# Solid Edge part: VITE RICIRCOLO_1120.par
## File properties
Subject: VITE RICIRCOLO 1120
Author: f_grande
Template: Normal.par
Last saved by: f_grande
Revision: 3
Application: Solid Edge
Material: Acciaio
Stile della faccia: Acciaio
Stile di riempimento: ANSI32(Acciaio)
Stile virtuale: Acciaio lavorato a macchina
Coef. of Thermal Exp: 0.0
Thermal Conductivity: 32.0
Specific Heat: 481.0
Modulus of Elasticity: 199947953000.0
Poisson's Ratio: 0.29
Yield Stress: 262000766.0
Ultimate Stress: 358527364.0
Elongation: 0.0
Tipo di contenuto documento: 0
Densità: 7833,000 kg/m^3
Precisione: 0,990
Document Number: KR0106
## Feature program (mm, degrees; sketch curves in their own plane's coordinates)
sketch for "unnamed Protrusion 1" plane through (0, 0, 0) normal (0, -1, 0) x-axis (1, 0, 0)
  circle centre (0, 0) radius 8
extrude "unnamed Protrusion 1" add finite 1120 along -normal
sketch for "ExtrudedCutout_1" #1 plane through (0, 0, 0) normal (0, -1, 0) x-axis (1, 0, 0)
  circle centre (0, 0) radius 5
sketch for "ExtrudedCutout_1" #2 plane through (0, 0, 0) normal (0, -1, 0) x-axis (1, 0, 0)
  circle centre (0, 0) radius 9.8339
extrude "ExtrudedCutout_1" cut finite 12 along -normal
sketch for "unnamed RevolvedCutout 1" plane through (0, 0, 0) normal (1, 0, 0) x-axis (0, 1, 0)
  line (3, 5) -> (4.1, 5)
  line (4.1, 5) -> (4.1, 4.6)
  line (4.1, 4.6) -> (3, 4.6)
  line (3, 4.6) -> (3, 5)
  dimension (linear) = 3
  dimension (linear) = 4.1
revolve "unnamed RevolvedCutout 1" cut full turn 360 deg
helix cutout "HelixCutout_2"  Pitch = 5 mm
sketch for "ExtrudedCutout_2" #1 plane through (0, 1120, 0) normal (0, 1, 0) x-axis (-1, 0, 0)
  circle centre (0, 0) radius 6
sketch for "ExtrudedCutout_2" #2 plane through (0, 1120, 0) normal (0, 1, 0) x-axis (-1, 0, 0)
  circle centre (0, 0) radius 9.9648
extrude "ExtrudedCutout_2" cut finite 54 along -normal
sketch for "ExtrudedCutout_3" #1 plane through (0, 1120, 0) normal (0, 1, 0) x-axis (-1, 0, 0)
  circle centre (0, 0) radius 5
sketch for "ExtrudedCutout_3" #2 plane through (0, 1120, 0) normal (0, 1, 0) x-axis (-1, 0, 0)
  circle centre (0, 0) radius 10.6518
extrude "ExtrudedCutout_3" cut finite 16 along -normal
thread "Filettatura_3"  ThreadDepth = 16 mm
chamfer "Smusso_1" setback 1
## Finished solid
Body 1: solid body, 18 faces, 20 edges, 4 vertices.
  Faces by surface: plane 9, cylinder 7, cone 1, spline 1
  Edges by curve: circle 16, line 2, spline 2
Bounding box of the edges (mm; curved faces can reach further): 16.000 x 1120.000 x 16.000, from (-8, 0, -8) to (8, 1120, 8).
Cylindrical faces by radius (mm): R4.6 x1, R5 x3, R6 x2, R8 x1
Conical faces (half-angle, radius in mm at the cone's reference point): 45 deg R5 x1
Planar faces by outward normal: +x 1, +y 4, -x 1, -y 3
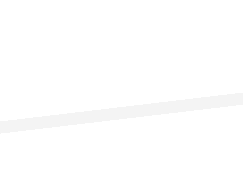
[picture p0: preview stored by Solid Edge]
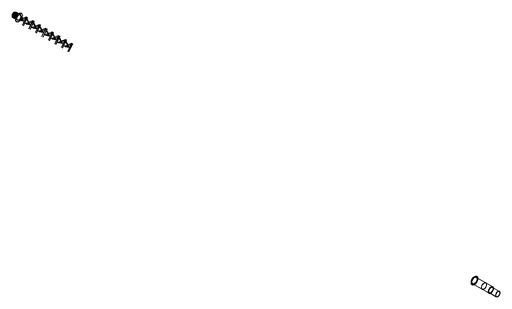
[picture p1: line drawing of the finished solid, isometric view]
